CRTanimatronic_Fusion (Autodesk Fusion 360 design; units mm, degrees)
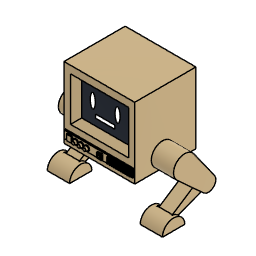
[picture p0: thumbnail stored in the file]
canvas "Canvas1"
sketch "Sketch2" plane through (0, 0, 0) normal (0, 1, 0) x axis (1, 0, 0)
  line L1 (3.0224, -3.2471) -> (-3.3287, -3.2471)
  line L2 (3.0224, 3.1161) -> (3.0224, -3.2471)
  line L3 (-3.3287, 3.1161) -> (3.0224, 3.1161)
  line L4 (-3.3287, -3.2471) -> (-3.3287, 3.1161)
  line L5 (1.8616, -2.2113) -> (-2.1377, -2.2113)
  line L6 (1.8616, 0.9941) -> (1.8616, -2.2113)
  line L7 (-2.1377, 0.9941) -> (1.8616, 0.9941)
  line L8 (-2.1377, -2.2113) -> (-2.1377, 0.9941)
  line L9 (2.5, -2.5495) -> (-2.6965, -2.5495)
  line L10 (2.5, 1.5) -> (2.5, -2.5495)
  line L11 (-2.6965, 1.5) -> (2.5, 1.5)
  line L12 (-2.6965, -2.5495) -> (-2.6965, 1.5)
  line L13 (2.9, 2) -> (-3.2, 2)
  line L14 (2.9, 2.7) -> (2.9, 2)
  line L15 (-3.2, 2.7) -> (2.9, 2.7)
  line L16 (-3.2, 2) -> (-3.2, 2.7)
  line L17 (2.9, 2.35) -> (-3.2, 2.35)
  point P18 (-3.2, 2.35)
  point P19 (2.9, 2.35)
  horizontal L1
  vertical L2
  horizontal L3
  vertical L4
  horizontal L5
  vertical L6
  horizontal L7
  vertical L8
  horizontal L9
  vertical L10
  horizontal L11
  vertical L12
  horizontal L13
  vertical L14
  horizontal L15
  vertical L16
  midpoint L16 P18
  midpoint L14 P19
canvas "Canvas1"
canvas "Canvas2"
extrude "Extrude1" new body sketch "Sketch2" profile of L1 L2 L3 L4 L5 L6 L7 L8 L9 L10 L11 L12 L13 L14 L15 L16 along normal blind 3 and against normal blind 2.5
sketch "Sketch3" plane through (0, -2.5, 0) normal (0, -1, 0) x axis (1, 0, 0)
  line L1 (-3.3287, -3.1161) -> (-3.3287, 3.2471)
  line L2 (3.0224, -3.1161) -> (-3.3287, -3.1161)
  line L3 (3.0224, 3.2471) -> (3.0224, -3.1161)
  line L4 (-3.3287, 3.2471) -> (3.0224, 3.2471)
  line L5 (2.4851, 2.5792) -> (-2.7433, 2.5792)
  line L6 (2.4851, -1.3522) -> (2.4851, 2.5792)
  line L7 (-2.7433, -1.3522) -> (2.4851, -1.3522)
  line L8 (-2.7433, 2.5792) -> (-2.7433, -1.3522)
  horizontal L5
  vertical L6
  horizontal L7
  vertical L8
extrude "Extrude2" cut sketch "Sketch3" profile of L5 L6 L7 L8 against normal blind 0.5
chamfer "Chamfer1" distance 0.5
sketch "Sketch4" plane through (0, -2.5, 0) normal (0, -1, 0) x axis (1, 0, 0)
  line L1 (2.4851, -1.3522) -> (2.4851, 2.5792)
  line L2 (-2.7433, -1.3522) -> (2.4851, -1.3522)
  line L3 (-2.7433, 2.5792) -> (-2.7433, -1.3522)
  line L4 (2.4851, 2.5792) -> (-2.7433, 2.5792)
  line L5 (-3.3287, -3.1161) -> (-3.3287, 3.2471)
  line L6 (3.0224, -3.1161) -> (-3.3287, -3.1161)
  line L7 (3.0224, 3.2471) -> (3.0224, -3.1161)
  line L8 (-3.3287, 3.2471) -> (3.0224, 3.2471)
  line L9 (2.9224, -1.9555) -> (-3.2287, -1.9555)
  line L10 (2.9224, -2.6621) -> (2.9224, -1.9555)
  line L11 (-3.2287, -2.6621) -> (2.9224, -2.6621)
  line L12 (-3.2287, -1.9555) -> (-3.2287, -2.6621)
  horizontal L9
  vertical L10
  horizontal L11
  vertical L12
  dimension "d10" distance L5 L12 = 0.1
  dimension "d11" distance L7 L10 = 0.1 (= "d10")
extrude "Extrude3" add sketch "Sketch4" profile of L9 L10 L11 L12 along normal blind 0.1
sketch "Sketch6" plane through (0, -2.6, 0) normal (0, -1, 0) x axis (1, 0, 0)
  line L1 (2.9224, -2.6621) -> (-3.2287, -2.6621)
  line L2 (2.9224, -1.9555) -> (2.9224, -2.6621)
  line L3 (-3.2287, -1.9555) -> (2.9224, -1.9555)
  line L4 (-3.2287, -2.6621) -> (-3.2287, -1.9555)
  line L5 (0.7, -2.05) -> (0.8, -2.05)
  line L6 (0.7, -2.6) -> (0.7, -2.05)
  line L7 (0.8, -2.6) -> (0.7, -2.6)
  line L8 (0.8, -2.05) -> (0.8, -2.6)
  point P8 (0.7, -2.6)
  point P9 (0.8, -2.6)
  horizontal L5
  vertical L6
  horizontal L7
  vertical L8
  dimension "d16" distance P8 P9 = 0.1
extrude "Extrude4" add sketch "Sketch6" profile of L5 L6 L7 L8 along normal blind 0.1
fillet "Fillet1" radius 0.02
rectangular_pattern "R-Pattern1" countU 11 uSpaceDistance -0.2 vSpaceDistance 0
sketch "Sketch7" plane through (0, -2.6, 0) normal (0, -1, 0) x axis (1, 0, 0)
  line L1 (2.58, -2.03) -> (2.52, -2.03)
  line L2 (2.62, -2.58) -> (2.62, -2.07)
  line L3 (2.52, -2.62) -> (2.58, -2.62)
  line L4 (2.48, -2.07) -> (2.48, -2.58)
  line L5 (2.18, -2.03) -> (2.12, -2.03)
  line L6 (2.22, -2.58) -> (2.22, -2.07)
  line L7 (2.12, -2.62) -> (2.18, -2.62)
  line L8 (2.08, -2.07) -> (2.08, -2.58)
  line L9 (1.78, -2.03) -> (1.72, -2.03)
  line L10 (1.82, -2.58) -> (1.82, -2.07)
  line L11 (1.72, -2.62) -> (1.78, -2.62)
  line L12 (1.68, -2.07) -> (1.68, -2.58)
  line L13 (1.38, -2.03) -> (1.32, -2.03)
  line L14 (1.42, -2.58) -> (1.42, -2.07)
  line L15 (1.32, -2.62) -> (1.38, -2.62)
  line L16 (1.28, -2.07) -> (1.28, -2.58)
  line L17 (0.98, -2.03) -> (0.92, -2.03)
  line L18 (1.02, -2.58) -> (1.02, -2.07)
  line L19 (0.92, -2.62) -> (0.98, -2.62)
  line L20 (0.88, -2.07) -> (0.88, -2.58)
  line L21 (2.9224, -2.6621) -> (-3.2287, -2.6621)
  line L22 (2.9224, -1.9555) -> (2.9224, -2.6621)
  line L23 (-3.2287, -1.9555) -> (2.9224, -1.9555)
  line L24 (-3.2287, -2.6621) -> (-3.2287, -1.9555)
  line L25 (0.78, -2.03) -> (0.72, -2.03)
  line L26 (0.82, -2.58) -> (0.82, -2.07)
  line L27 (0.72, -2.62) -> (0.78, -2.62)
  line L28 (0.68, -2.07) -> (0.68, -2.58)
  line L29 (1.18, -2.03) -> (1.12, -2.03)
  line L30 (1.22, -2.58) -> (1.22, -2.07)
  line L31 (1.12, -2.62) -> (1.18, -2.62)
  line L32 (1.08, -2.07) -> (1.08, -2.58)
  line L33 (1.58, -2.03) -> (1.52, -2.03)
  line L34 (1.62, -2.58) -> (1.62, -2.07)
  line L35 (1.52, -2.62) -> (1.58, -2.62)
  line L36 (1.48, -2.07) -> (1.48, -2.58)
  line L37 (1.98, -2.03) -> (1.92, -2.03)
  line L38 (2.02, -2.58) -> (2.02, -2.07)
  line L39 (1.92, -2.62) -> (1.98, -2.62)
  line L40 (1.88, -2.07) -> (1.88, -2.58)
  line L41 (2.38, -2.03) -> (2.32, -2.03)
  line L42 (2.42, -2.58) -> (2.42, -2.07)
  line L43 (2.32, -2.62) -> (2.38, -2.62)
  line L44 (2.28, -2.07) -> (2.28, -2.58)
  line L45 (2.78, -2.03) -> (2.72, -2.03)
  line L46 (2.82, -2.58) -> (2.82, -2.07)
  line L47 (2.72, -2.62) -> (2.78, -2.62)
  line L48 (2.68, -2.07) -> (2.68, -2.58)
  line L49 (0.25, -2.1249) -> (-0.2, -2.1249)
  line L50 (0.25, -2.5873) -> (0.25, -2.1249)
  line L51 (-0.2, -2.5873) -> (0.25, -2.5873)
  line L52 (-0.2, -2.1249) -> (-0.2, -2.5873)
  line L53 (0.202, -2.1795) -> (-0.1512, -2.1795)
  line L54 (0.202, -2.5327) -> (0.202, -2.1795)
  line L55 (-0.1512, -2.5327) -> (0.202, -2.5327)
  line L56 (-0.1512, -2.1795) -> (-0.1512, -2.5327)
  line L57 (-0.138, -2.3495) -> (0.0188, -2.3495)
  line L58 (-0.138, -2.1927) -> (-0.138, -2.3495)
  line L59 (0.0188, -2.1927) -> (-0.138, -2.1927)
  line L60 (0.0188, -2.3495) -> (0.0188, -2.1927)
  line L61 (0.1888, -2.1927) -> (0.032, -2.1927)
  line L62 (0.1888, -2.3495) -> (0.1888, -2.1927)
  line L63 (0.032, -2.3495) -> (0.1888, -2.3495)
  line L64 (0.032, -2.1927) -> (0.032, -2.3495)
  line L65 (0.0188, -2.3627) -> (-0.138, -2.3627)
  line L66 (0.0188, -2.5195) -> (0.0188, -2.3627)
  line L67 (-0.138, -2.5195) -> (0.0188, -2.5195)
  line L68 (-0.138, -2.3627) -> (-0.138, -2.5195)
  line L69 (0.1888, -2.3627) -> (0.032, -2.3627)
  line L70 (0.1888, -2.5195) -> (0.1888, -2.3627)
  line L71 (0.032, -2.5195) -> (0.1888, -2.5195)
  line L72 (0.032, -2.3627) -> (0.032, -2.5195)
  arc A1 centre (2.52, -2.07) radius 0.04 clockwise from (2.48, -2.07) to (2.52, -2.03)
  arc A2 centre (2.58, -2.07) radius 0.04 clockwise from (2.58, -2.03) to (2.62, -2.07)
  arc A3 centre (2.58, -2.58) radius 0.04 clockwise from (2.62, -2.58) to (2.58, -2.62)
  arc A4 centre (2.52, -2.58) radius 0.04 clockwise from (2.52, -2.62) to (2.48, -2.58)
  arc A5 centre (2.12, -2.07) radius 0.04 clockwise from (2.08, -2.07) to (2.12, -2.03)
  arc A6 centre (2.18, -2.07) radius 0.04 clockwise from (2.18, -2.03) to (2.22, -2.07)
  arc A7 centre (2.18, -2.58) radius 0.04 clockwise from (2.22, -2.58) to (2.18, -2.62)
  arc A8 centre (2.12, -2.58) radius 0.04 clockwise from (2.12, -2.62) to (2.08, -2.58)
  arc A9 centre (1.72, -2.07) radius 0.04 clockwise from (1.68, -2.07) to (1.72, -2.03)
  arc A10 centre (1.78, -2.07) radius 0.04 clockwise from (1.78, -2.03) to (1.82, -2.07)
  arc A11 centre (1.78, -2.58) radius 0.04 clockwise from (1.82, -2.58) to (1.78, -2.62)
  arc A12 centre (1.72, -2.58) radius 0.04 clockwise from (1.72, -2.62) to (1.68, -2.58)
  arc A13 centre (1.32, -2.07) radius 0.04 clockwise from (1.28, -2.07) to (1.32, -2.03)
  arc A14 centre (1.38, -2.07) radius 0.04 clockwise from (1.38, -2.03) to (1.42, -2.07)
  arc A15 centre (1.38, -2.58) radius 0.04 clockwise from (1.42, -2.58) to (1.38, -2.62)
  arc A16 centre (1.32, -2.58) radius 0.04 clockwise from (1.32, -2.62) to (1.28, -2.58)
  arc A17 centre (0.92, -2.07) radius 0.04 clockwise from (0.88, -2.07) to (0.92, -2.03)
  arc A18 centre (0.98, -2.07) radius 0.04 clockwise from (0.98, -2.03) to (1.02, -2.07)
  arc A19 centre (0.98, -2.58) radius 0.04 clockwise from (1.02, -2.58) to (0.98, -2.62)
  arc A20 centre (0.92, -2.58) radius 0.04 clockwise from (0.92, -2.62) to (0.88, -2.58)
  arc A21 centre (0.72, -2.07) radius 0.04 clockwise from (0.68, -2.07) to (0.72, -2.03)
  arc A22 centre (0.78, -2.07) radius 0.04 clockwise from (0.78, -2.03) to (0.82, -2.07)
  arc A23 centre (0.78, -2.58) radius 0.04 clockwise from (0.82, -2.58) to (0.78, -2.62)
  arc A24 centre (0.72, -2.58) radius 0.04 clockwise from (0.72, -2.62) to (0.68, -2.58)
  arc A25 centre (1.12, -2.07) radius 0.04 clockwise from (1.08, -2.07) to (1.12, -2.03)
  arc A26 centre (1.18, -2.07) radius 0.04 clockwise from (1.18, -2.03) to (1.22, -2.07)
  arc A27 centre (1.18, -2.58) radius 0.04 clockwise from (1.22, -2.58) to (1.18, -2.62)
  arc A28 centre (1.12, -2.58) radius 0.04 clockwise from (1.12, -2.62) to (1.08, -2.58)
  arc A29 centre (1.52, -2.07) radius 0.04 clockwise from (1.48, -2.07) to (1.52, -2.03)
  arc A30 centre (1.58, -2.07) radius 0.04 clockwise from (1.58, -2.03) to (1.62, -2.07)
  arc A31 centre (1.58, -2.58) radius 0.04 clockwise from (1.62, -2.58) to (1.58, -2.62)
  arc A32 centre (1.52, -2.58) radius 0.04 clockwise from (1.52, -2.62) to (1.48, -2.58)
  arc A33 centre (1.92, -2.07) radius 0.04 clockwise from (1.88, -2.07) to (1.92, -2.03)
  arc A34 centre (1.98, -2.07) radius 0.04 clockwise from (1.98, -2.03) to (2.02, -2.07)
  arc A35 centre (1.98, -2.58) radius 0.04 clockwise from (2.02, -2.58) to (1.98, -2.62)
  arc A36 centre (1.92, -2.58) radius 0.04 clockwise from (1.92, -2.62) to (1.88, -2.58)
  arc A37 centre (2.32, -2.07) radius 0.04 clockwise from (2.28, -2.07) to (2.32, -2.03)
  arc A38 centre (2.38, -2.07) radius 0.04 clockwise from (2.38, -2.03) to (2.42, -2.07)
  arc A39 centre (2.38, -2.58) radius 0.04 clockwise from (2.42, -2.58) to (2.38, -2.62)
  arc A40 centre (2.32, -2.58) radius 0.04 clockwise from (2.32, -2.62) to (2.28, -2.58)
  arc A41 centre (2.72, -2.07) radius 0.04 clockwise from (2.68, -2.07) to (2.72, -2.03)
  arc A42 centre (2.78, -2.07) radius 0.04 clockwise from (2.78, -2.03) to (2.82, -2.07)
  arc A43 centre (2.78, -2.58) radius 0.04 clockwise from (2.82, -2.58) to (2.78, -2.62)
  arc A44 centre (2.72, -2.58) radius 0.04 clockwise from (2.72, -2.62) to (2.68, -2.58)
  horizontal L49
  vertical L50
  horizontal L51
  vertical L52
  horizontal L53
  vertical L54
  horizontal L55
  vertical L56
  horizontal L57
  vertical L58
  horizontal L59
  vertical L60
  equal L57 L60
  dimension "d25" distance L49 L53 = 0.0546
  dimension "d30" distance L51 L55 = 0.0546 (= "d25")
  dimension "d31" distance L54 L70 = 0.0132 (= "d32")
  dimension "d32" distance L56 L68 = 0.0132
  dimension "d33" distance L53 L61 = 0.0132 (= "d32")
  dimension "d34" distance L55 L71 = 0.0132 (= "d32")
  dimension "d35" distance L60 L64 = 0.0132 (= "d32")
  dimension "d28" R-Pattern1-uDistance = 0.17
  dimension "d29" R-Pattern1-vDistance = -0.17
extrude "Extrude5" add sketch "Sketch7" profile of L49 L50 L51 L52 L53 L54 L55 L56 along normal blind 0.1
extrude "Extrude6" add sketch "Sketch7" profile of L57 L58 L59 L60 L61 L62 L63 L64 L65 L66 L67 L68 L69 L70 L71 L72 along normal blind 0.05
sketch "Sketch8" plane through (0, -2.6, 0) normal (0, -1, 0) x axis (1, 0, 0)
  circle C1 centre (-2.17, -2.36) radius 0.1476
  circle C2 centre (-2.17, -2.36) radius 0.191
  circle C3 centre (-2.17, -2.36) radius 0.2335
  concentric C1 C2
  concentric C1 C3
extrude "Extrude7" add sketch "Sketch8" profile of C2 C3 along normal blind 0.05
extrude "Extrude8" add sketch "Sketch8" profile of C1 along normal blind 0.25
rectangular_pattern "R-Pattern2" uSpaceDistance 0.5 vSpaceDistance 0
sketch "Sketch9" plane through (0, -2.6, 0) normal (0, -1, 0) x axis (1, 0, 0)
  line L1 (-2.4623, -2.0737) -> (-2.9179, -2.0737)
  line L2 (-2.4623, -2.6088) -> (-2.4623, -2.0737)
  line L3 (-2.9179, -2.6088) -> (-2.4623, -2.6088)
  line L4 (-2.9179, -2.0737) -> (-2.9179, -2.6088)
  horizontal L1
  vertical L2
  horizontal L3
  vertical L4
extrude "Extrude9" add sketch "Sketch9" along normal blind 0.1
fillet "Fillet3" radius 0.02
fillet "Fillet4" radius 0.02
fillet "Fillet2" radius 0.02
sketch "Sketch1" plane through (3.0224, 0, 0) normal (1, 0, 0) x axis (0, 1, 0)
  line L1 (3, -3.1161) -> (-2.5, -3.1161)
  line L2 (3, 3.2471) -> (3, -3.1161)
  line L3 (-2.5, 3.2471) -> (3, 3.2471)
  line L4 (-2.5, -3.1161) -> (-2.5, 3.2471)
  line L5 (-0.6782, -2.7389) -> (1.6852, -4.8951)
  line L6 (2.6695, -4.0215) -> (0.8093, -1.4187)
  circle C1 centre (-0.0043, -2.0001) radius 1
  circle C2 centre (2.1312, -4.4063) radius 0.6617
  point P8 (1.6852, -4.8951)
  point P9 (-0.6782, -2.7389)
  point P10 (0.8093, -1.4187)
  point P11 (2.6695, -4.0215)
  coincident C2 P8
  coincident C1 P9
  coincident C1 P10
  coincident C2 P11
  tangent C2 L6
  tangent C1 L5
  tangent C1 L6
  tangent C2 L5
  dimension "d56" diameter C1 = 2
extrude "Extrude1" new body sketch "Sketch1" profile of L1 C1 C2 L5 L6 along normal blind 2
work_plane "WorkPlane1" sketch "Sketch1" AlongDistance 0.4
sketch "Sketch1" plane through (3.4224, 0, 0) normal (1, 0, 0) x axis (0, 1, 0)
  line L1 (1.8231, -3.9366) -> (-1.0972, -5.8519)
  line L2 (2.3296, -4.9317) -> (-0.9374, -6.1657)
  circle C1 centre (2.1312, -4.4063) radius 0.6617
  circle C2 centre (2.1312, -4.4063) radius 0.5617
  circle C3 centre (-1, -6) radius 0.1772
  point P5 (-1.0972, -5.8519)
  point P6 (1.8231, -3.9366)
  point P7 (-0.9374, -6.1657)
  point P8 (2.3296, -4.9317)
  coincident C3 P5
  coincident C2 P6
  tangent C2 L1
  coincident C3 P7
  coincident C2 P8
  tangent C2 L2
  tangent C3 L1
  tangent C3 L2
  dimension "d60" = -0.1
extrude "Extrude1" new body sketch "Sketch1" along normal blind 1.2
combine "Combine1"
offset_faces "OffsetFaces1" distance -0.1
sketch "Sketch1" plane through (4.6224, 0, 0) normal (1, 0, 0) x axis (0, 1, 0)
  line L1 (2.3296, -4.9317) -> (-0.9374, -6.1657)
  line L2 (-1.0972, -5.8519) -> (1.8231, -3.9366)
  line L3 (0, -6.5) -> (-2, -6.5)
  arc A1 centre (-1, -6) radius 0.1772 clockwise from (-0.9374, -6.1657) to (-1.0972, -5.8519)
  arc A2 centre (2.1312, -4.4063) radius 0.5617 clockwise from (1.8231, -3.9366) to (2.3296, -4.9317)
  arc A3 centre (-1, -6.5) radius 1 clockwise from (-2, -6.5) to (0, -6.5)
  horizontal L3
extrude "Extrude1" new body sketch "Sketch1" profile of A1 L1 L2 L3 A3 to an object Side2Offset 0
combine "Combine1"
offset_faces "OffsetFaces1" distance -0.1
work_axis "WorkAxis1"
revolve "Revolve1" AlongAngle -20
offset_faces "OffsetFaces2" distance -0.156
work_axis "WorkAxis1"
sketch "Sketch3" plane through (3.3224, 0, 0) normal (1, 0, 0) x axis (0, 1, 0)
  line L1 (1.0554, -4.3205) -> (1.7683, -3.853)
  line L2 (1.6852, -4.8951) -> (1.0554, -4.3205)
  line L3 (0.4242, -3.7446) -> (2.1784, -3.7446)
  line L4 (-0.6782, -2.7389) -> (1.6852, -4.8951)
  arc A1 centre (2.1312, -4.4063) radius 0.6617 clockwise from (2.6695, -4.0215) to (1.6852, -4.8951)
  arc A2 centre (2.1312, -4.4063) radius 0.6617 clockwise from (1.7683, -3.853) to (2.6695, -4.0215)
  circle C1 centre (2.1312, -4.4063) radius 0.6617
  point P8 (0.4242, -3.7446)
  horizontal L3
  tangent L3 C1
  coincident P8 L4
extrude "Extrude2" cut sketch "Sketch3" to an object
mirror_component "MirrorComponent1"
component_from_bodies "Body->Comp"
position "Position1" sketch "Sketch7"
derived_instance "DerivedInstance1"
derived_instance "DerivedInstance2"
derived_instance "DerivedInstance3"
ground "Pin2"
ground "Pin3"
place_component sketch "Sketch2"
sketch "Sketch2" plane through (3.0224, 0, 0) normal (1, 0, 0) x axis (0, 1, 0)
  line L1 (-3, 4.9201) -> (-5.3401, 4.9201)
  line L2 (-3, 0) -> (-3, 4.9201)
  line L3 (-5.3401, 0) -> (-3, 0)
  line L4 (-5.3401, 4.9201) -> (-5.3401, 0)
  line L5 (3, -3.1161) -> (-2.5, -3.1161)
  line L6 (3, 3.2471) -> (3, -3.1161)
  line L7 (-2.5, 3.2471) -> (3, 3.2471)
  line L8 (-2.5, -3.1161) -> (-2.5, 3.2471)
  horizontal L1
  vertical L2
  horizontal L3
  vertical L4
extrude "Extrude1" new body sketch "Sketch2" profile of L1 L2 L3 L4 against normal blind 1
as_built_joint "As-built10" OffsetX 0 OffsetY 0 OffsetZ 0 AngleZ 0
as_built_joint "As-built11" OffsetX 0 OffsetY 0 OffsetZ 0 AngleZ 0 RotateMinimum -20 RotateMaximum 90 RotateRest 0
as_built_joint "As-built12" OffsetX 0 OffsetY 0 OffsetZ 0 AngleZ 0
as_built_joint "As-built13" OffsetX 0 OffsetY 0 OffsetZ 0 AngleZ 0 SlideMinimum 0 SlideRest 0
ground "Pin4"
as_built_joint "As-built14" OffsetX 0 OffsetY 0 OffsetZ 0 AngleZ 0
as_built_joint "As-built15" OffsetX 0 OffsetY 0 OffsetZ 0 AngleZ 0 RotateRest 0 RotateMinimum -50 RotateMaximum 50
as_built_joint "As-built16" OffsetX 0 OffsetY 0 OffsetZ 0 AngleZ 0
sketch "Sketch1" plane through (0, -2, -2) normal (0, -1, 0) x axis (1, 0, 0)
  line L1 (1.9851, 4.0792) -> (1.9851, 1.1478)
  line L2 (-2.2433, 4.0792) -> (1.9851, 4.0792)
  line L3 (-2.2433, 1.1478) -> (-2.2433, 4.0792)
  line L4 (1.9851, 1.1478) -> (-2.2433, 1.1478)
  curve K1 (-1.2433, 2.3491) -> (-1.2433, 3.6271)
  curve K2 (-1.0176, 2.9881) -> (-1.469, 2.9881)
  curve K3 (0.9861, 2.3499) -> (0.984, 3.6279)
  curve K4 (1.2108, 2.9893) -> (0.7594, 2.9885)
  line L5 (0.7351, 2.0792) -> (-0.9933, 2.0792)
  line L6 (0.7351, 1.7508) -> (0.7351, 2.0792)
  line L7 (-0.9933, 1.7508) -> (0.7351, 1.7508)
  line L8 (-0.9933, 2.0792) -> (-0.9933, 1.7508)
  closed curve K5 centre (-1.2433, 2.9881)
  closed curve K6 centre (0.9851, 2.9889)
  point P7 (-1.2433, 3.6271)
  point P8 (-1.2433, 2.3491)
  point P9 (-1.469, 2.9881)
  point P10 (-1.0176, 2.9881)
  point P12 (0.984, 3.6279)
  point P13 (0.9861, 2.3499)
  point P14 (0.7594, 2.9885)
  point P15 (1.2108, 2.9893)
  point P6 (-1.2433, 2.9881)
  point P11 (0.9851, 2.9889)
  point P16 (-0.9933, 2.0792)
  point P17 (0.7351, 2.0792)
  coincident K5 P7
  coincident K5 P8
  coincident K5 P9
  coincident K5 P10
  parallel L3 K1
  coincident K6 P12
  coincident K6 P13
  coincident K6 P14
  coincident K6 P15
  horizontal L5
  vertical L6
  horizontal L7
  vertical L8
  dimension "d186" distance L3 P6 = 1
  dimension "d187" distance L1 P11 = 1 (= "d186")
  dimension "d188" distance L2 L5 = 2
  dimension "d189" distance P6 P16 = 0.25
  dimension "d190" distance P11 P17 = 0.25 (= "d189")
sketch "Sketch2" plane through (0, -2, -2) normal (0, -1, 0) x axis (1, 0, 0)
sketch "Sketch3" plane through (0, -2, -2) normal (0, -1, 0) x axis (1, 0, 0)
extrude "Extrude1" new body sketch "Sketch1" profile of K5 K6 L5 L6 L7 L8 along normal blind 0.001
as_built_joint "As-built18"
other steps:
base_feature "Base Feature"
derived_base_feature "Derived Base Feature1"
derived_base_feature "Derived Base Feature1"
derived_base_feature "Derived Base Feature1"
create_component "CreateComponent1"
create_component "CreateComponent2"
create_component "CreateComponent3"
create_component "CreateComponent4"
create_component "CreateComponent5"
create_component "CreateComponent6"
create_component "CreateComponent7"
create_component "CreateComponent8"
remove_body "RemoveBody1"
create_component "CreateComponent9" sketch "Sketch2"
create_component "CreateComponent10"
